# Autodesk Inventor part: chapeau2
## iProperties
Shininess: 64.0
Length Units: 11269
Angle Units: 11279
Time Units: 11290
Mass Units: 11283
Length Display Precision: 3
Angle Display Precision: 2
Compacted: True
Part Number: chapeau2
Document SubType Name: Modeling
Created: 2005-01
Material: Par défaut
Designer: Flavien MARTY
Density: 0.0
Volumn: 0.0
Area: 0.0
PropertySet Name: Model Information
Control State: 0
Master: False
Checked Out: False
Norme de conversion: STEP AP203
Nom du fichier: chapeau2.STEP
Préprocesseur: SolidWorks 2001039
Postprocesseur: Build: Release: 6 RTM Build: 90b - Date: Tue 09/24/2002
Unités envoyées: MILLIMETERS
Incertitude: 0.0
Author: Flavien MARTY
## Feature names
1. Base1
